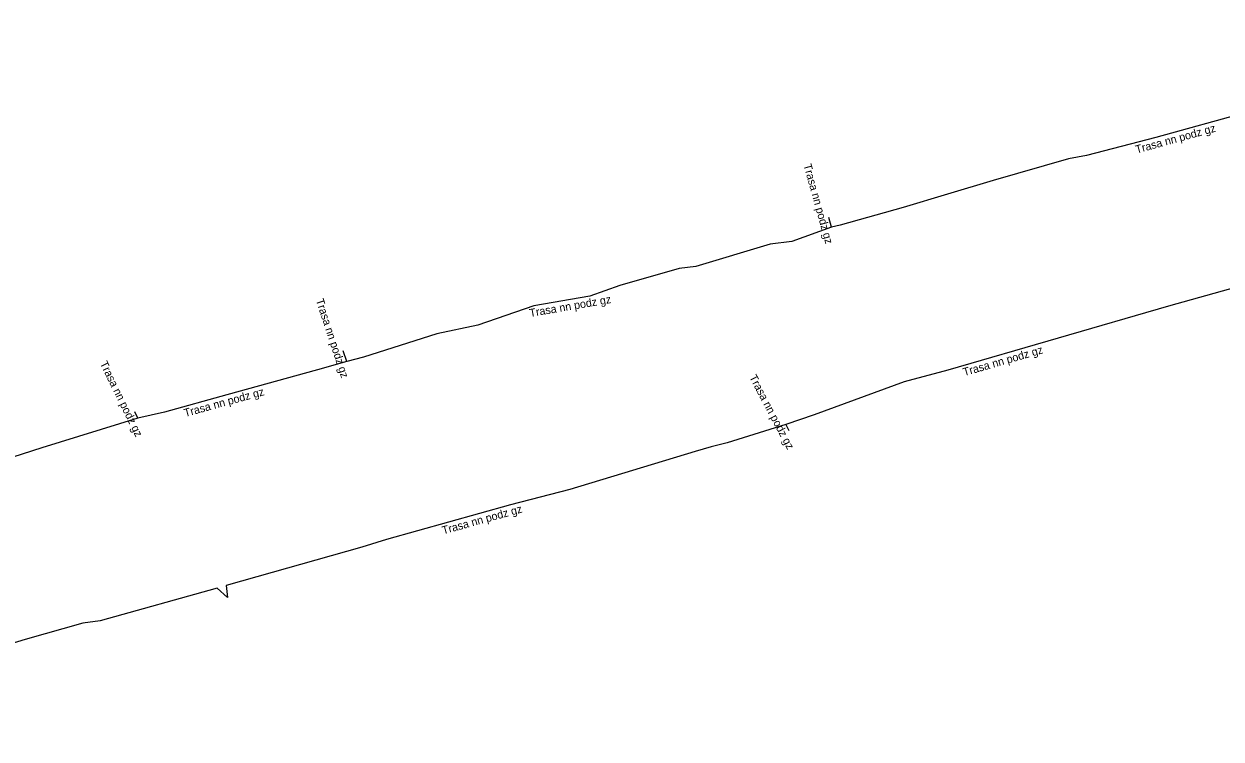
# Model space of a CAD drawing. Extents: x -690200 to -689130, y -975255 to -974631.
# Drawn here: x -690124.3 to -690049.5, y -975183.8 to -975139.2 of the extents above; entities that cross this region are included whole.
import ezdxf

# ---------------------------------------------------------------- set-up
doc = ezdxf.new("R2010")
doc.units = 0
doc.layers.add('Popiskový text - Ostatní atributy Trasy', color=7, linetype='Continuous')
doc.layers.add('Spojnice NN', color=7, linetype='Continuous')

msp = doc.modelspace()

# ---------------------------------------------------------------- linework, layer by layer
at = {"layer": 'Spojnice NN'}
for points in [[(-690028.61, -975139.19), (-690035.08, -975141.16), (-690036.8, -975141.49), (-690044.44, -975143.76), (-690046.96, -975144.39), (-690047.86, -975144.7), (-690053.58, -975146.28), (-690057.91, -975147.41), (-690059.03, -975147.62), (-690063.73, -975148.97), (-690066.58, -975149.83), (-690069.36, -975150.66), (-690073.3, -975151.75), (-690073.83, -975151.88)], [(-690073.83, -975151.88), (-690074, -975151.27)], [(-690073.83, -975151.88), (-690076.31, -975152.78), (-690077.66, -975152.94), (-690082.31, -975154.34), (-690083.34, -975154.47), (-690087.05, -975155.52), (-690088.92, -975156.19), (-690092.43, -975156.8), (-690095.92, -975158.01), (-690098.48, -975158.55), (-690103.07, -975160), (-690104.111, -975160.27)], [(-690047.12, -975155.23), (-690052.79, -975156.81), (-690066.57, -975160.81), (-690069.29, -975161.54), (-690074.92, -975163.6), (-690076.69, -975164.21)], [(-690104.111, -975160.27), (-690104.33, -975159.6)], [(-690104.111, -975160.27), (-690105.95, -975160.79), (-690111.61, -975162.35), (-690115.5, -975163.44), (-690117.16, -975163.8)], [(-690117.16, -975163.8), (-690117.35, -975163.41)], [(-690117.16, -975163.8), (-690123.15, -975165.66), (-690128.04, -975167.23), (-690133.9, -975168.58), (-690140.5, -975170.4), (-690142.26, -975170.71), (-690144.51, -975171.38), (-690147.12, -975171.97), (-690150.1, -975172.77), (-690152.23, -975173.28), (-690154.06, -975173.21)], [(-690076.69, -975164.21), (-690080.36, -975165.34), (-690081.35, -975165.59), (-690082.34, -975165.89), (-690090.18, -975168.27), (-690093.89, -975169.23), (-690101.64, -975171.39), (-690103.17, -975171.87), (-690111.65, -975174.26), (-690111.56, -975175)], [(-690076.69, -975164.21), (-690076.5, -975164.57)], [(-690111.56, -975175), (-690112.2, -975174.43), (-690119.52, -975176.46), (-690120.59, -975176.62), (-690124.2, -975177.63), (-690135.97, -975181.22), (-690140.43, -975182.47), (-690143.46, -975183.43), (-690143.63, -975183.85)]]:
    msp.add_lwpolyline(points, dxfattribs=at)

# ---------------------------------------------------------------- texts
at = {"layer": 'Popiskový text - Ostatní atributy Trasy'}
for rotation, p in [(15.44142, (-690054.774, -975147.284)), (285.57254, (-690075.586, -975147.998)), (288.13941, (-690106.05, -975156.438)), (9.85892, (-690092.658, -975157.499)), (16.18673, (-690065.542, -975161.189)), (295.97439, (-690119.545, -975160.389)), (297.8241, (-690078.988, -975161.25)), (15.40919, (-690114.205, -975163.74)), (15.57367, (-690098.085, -975171.074))]:
    msp.add_text('Trasa nn podz gz', height=0.5, rotation=rotation, dxfattribs=at).set_placement(p)

doc.saveas('drawing.dxf')
